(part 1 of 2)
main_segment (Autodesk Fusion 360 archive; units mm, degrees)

design "main_segment" references "mounting plate"
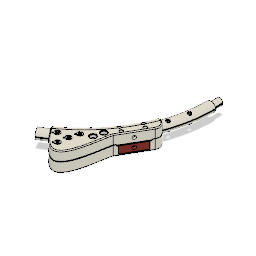
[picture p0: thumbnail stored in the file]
sketch "profile25mm" plane through (0, 0, 0) normal (0, 0, 1) x axis (1, 0, 0)
  line L1 (307.6864, 0) -> (0, 0)
  line L2 (284.5852, 6.2462) -> (284.5852, -6.2452)
  line L3 (286.5852, -8.1498) -> (286.5852, 8.1498)
  line L4 (286.6852, -8.0748) -> (286.6852, 8.0748)
  line L5 (288.5852, -6.4868) -> (288.5852, 6.4868)
  line L6 (281.1852, 6.0452) -> (281.1852, 6.2452)
  line L7 (280.7852, 5.8452) -> (280.9852, 5.8452)
  line L8 (280.3368, 6.812) -> (280.7852, 7.3155)
  line L9 (281.1852, -6.0452) -> (281.1852, -6.2452)
  line L10 (280.7852, -5.8452) -> (280.9852, -5.8452)
  line L11 (280.3368, -6.812) -> (280.7852, -7.3155)
  line L12 (284.1852, 5.6456) -> (284.1852, 6.2456)
  line L13 (282.5852, 5.4456) -> (283.9852, 5.4456)
  line L14 (282.3852, 6.2456) -> (282.3852, 5.6456)
  line L15 (284.1852, -5.6452) -> (284.1852, -6.2452)
  line L16 (282.5852, -5.4452) -> (283.9852, -5.4452)
  line L17 (282.3852, -6.2452) -> (282.3852, -5.6452)
  line L18 (282.3852, 6.2456) -> (281.1852, 6.2452)
  line L19 (284.5852, 6.2462) -> (284.1852, 6.2456)
  line L20 (282.3852, -6.2452) -> (281.1852, -6.2452)
  line L21 (284.5852, -6.2452) -> (284.1852, -6.2452)
  arc A1 centre (289, 0) radius 8.5 clockwise from (286.5852, 8.1498) to (286.5852, -8.1498)
  arc A2 centre (289, 0) radius 11 clockwise from (280.7852, 7.3155) to (280.7852, -7.3155)
  arc A3 centre (289, 0) radius 8.4 clockwise from (286.6852, 8.0748) to (286.6852, -8.0748)
  arc A4 centre (289, 0) radius 6.5 clockwise from (288.5852, 6.4868) to (288.5852, -6.4868)
  arc A5 centre (280.7705, 6.4258) radius 0.5808 clockwise from (280.7852, 5.8452) to (280.3368, 6.812)
  arc A6 centre (280.7705, -6.4258) radius 0.5808 clockwise from (280.3368, -6.812) to (280.7852, -5.8452)
  arc A7 centre (282.5852, 5.6456) radius 0.2 clockwise from (282.5852, 5.4456) to (282.3852, 5.6456)
  arc A8 centre (283.9852, 5.6456) radius 0.2 clockwise from (284.1852, 5.6456) to (283.9852, 5.4456)
  arc A9 centre (282.5852, -5.6452) radius 0.2 clockwise from (282.3852, -5.6452) to (282.5852, -5.4452)
  arc A10 centre (283.9852, -5.6452) radius 0.2 clockwise from (283.9852, -5.4452) to (284.1852, -5.6452)
  arc A11 centre (280.9852, -6.0452) radius 0.2 clockwise from (280.9852, -5.8452) to (281.1852, -6.0452)
  arc A12 centre (280.9852, 6.0452) radius 0.2 clockwise from (281.1852, 6.0452) to (280.9852, 5.8452)
  point P1 (0, 0)
  point P3 (0, 0)
  point P2 (289, 0)
  point P17 (280.7852, 7.3155)
  point P26 (280.7852, -7.3155)
  point P19 (280.7852, 5.8452)
  point P23 (280.7852, -5.8452)
  point P20 (280.3368, 6.812)
  point P25 (280.3368, -6.812)
  point P29 (282.3852, 5.4456)
  point P33 (282.3852, -5.4452)
  point P32 (284.1852, -5.4452)
  point P7 (289, 0)
  point P27 (282.3852, 6.2456)
  point P28 (284.1852, 6.2456)
  point P30 (282.3852, -6.2452)
  coincident P1 P3
  horizontal L1
  coincident P2 L1
  concentric A1 A2
  perpendicular L1 L3
  horizontal L20
  vertical L6
  horizontal L7
  tangent A2 L8
  tangent L8 A5
  vertical L9
  horizontal L10
  symmetric L1 P17 P26
  symmetric L1 P19 P23
  symmetric L1 P20 P25
  symmetric L1 A5 A6
  vertical L12
  horizontal L13
  vertical L14
  vertical L15
  horizontal L16
  vertical L17
  coincident P29 L13
  coincident P29 L14
  tangent L13 A7
  tangent L14 A7
  tangent L12 A8
  tangent L13 A8
  equal A7 A8
  coincident P33 L16
  coincident P33 L17
  tangent L16 A9
  tangent L17 A9
  equal A7 A9
  coincident P32 L15
  coincident P32 L16
  tangent L15 A10
  tangent L16 A10
  equal A7 A10
  tangent L9 A11
  tangent L10 A11
  equal A7 A11
  tangent L6 A12
  tangent L7 A12
  equal A7 A12
  collinear L20 L21
  dimension "d1" diameter A2 = 22
  dimension "d5" diameter A1 = 17
  dimension "d10" distance L2 L3 = 2
  dimension "d11" = -0.1
  dimension "d12" = -2
  dimension "d13" distance P1 P7 = 289
  dimension "d58" distance P27 P28 = 1.8
  dimension "d59" distance P27 P29 = 0.8
  dimension "d60" distance L2 L12 = 0.4
  dimension "d61" distance P32 P33 = 1.8
  dimension "d62" distance P30 P33 = 0.8
  dimension "d63" distance L2 L15 = 0.4
  dimension "d64" radius A7 = 0.2
revolve "Revolve1" sketch "profile25mm" AlongAngle 60 bodies "profile"
revolve "Revolve2" sketch "profile25mm" AlongAngle 4
revolve "Revolve3" sketch "profile25mm" AlongAngle -4
chamfer "Chamfer1" distance 1
chamfer "Chamfer2" distance 1.9
work_plane "WorkPlane1"
sketch "middle plane" plane through (272.3575, 0.0002, 35.882) normal (0, -1, 0) x axis (1, 0, 0)
  line L1 (-131.9649, 207.2851) -> (-122.3575, 223.9256)
  line L2 (14.6269, -55.9499) -> (23.3204, -56.5578)
  line L3 (13.6973, -54.8824) -> (14.6269, -55.9499)
  line L4 (25.0425, -35.882) -> (27.6425, -35.882)
  line L5 (8.4277, -35.882) -> (14.3277, -35.882)
  line L6 (24.3861, -55.6299) -> (23.3204, -56.5578)
  line L7 (-115.0265, 216.6233) -> (-113.7806, 218.7813)
  line L8 (17.5, -45.882) -> (24.8743, -45.882)
  line L9 (-132.1891, 206.8968) -> (-131.9649, 207.2851)
  line L10 (-132.2627, 206.7695) -> (-132.1891, 206.8968)
  line L11 (7.8322, -35.882) -> (7.9792, -35.882)
  line L12 (7.9792, -35.882) -> (8.4277, -35.882)
  arc A1 centre (-272.3575, -35.882) radius 286.6852 clockwise from (14.3277, -35.882) to (13.6973, -54.8824)
  arc A2 centre (-272.3575, -35.882) radius 297.4 clockwise from (25.0425, -35.882) to (24.3861, -55.6299)
  arc A3 centre (-272.3575, -35.882) radius 300 clockwise from (-122.3575, 223.9256) to (27.6425, -35.882)
  arc A4 centre (-272.3575, -35.882) radius 280.1897 clockwise from (-132.2627, 206.7695) to (7.8322, -35.882)
  point P14 (-113.7806, 218.7813)
  point P16 (24.8743, -45.882)
  coincident A3 P14
  parallel L1 L7
  coincident A2 P16
  parallel L4 L8
  dimension "d25" distance L1 L7 = 10
  dimension "d33" distance L4 L8 = 10
work_plane "WorkPlane2"
sketch "hole1" plane through (158.5769, 0.0002, 254.6632) normal (0.5286, 0, 0.8489) x axis (0, 1, 0)
  circle C1 centre (0, 0) radius 2.05
  circle C2 centre (0, 0) radius 1.05
  point P1 (0, 0)
  point P2 (0, 0)
  coincident P1 P2
  concentric C1 C2
  dimension "d26" diameter C1 = 4.1
  dimension "d27" diameter C2 = 2.1
extrude "Extrude2" cut sketch "hole1" along a picked direction blind -1
extrude "Extrude3" cut sketch "hole1" profile of C2 along a picked direction blind -3
work_plane "WorkPlane3"
sketch "hole2" plane through (297.2318, 0.0002, -10) normal (0.9994, 0, -0.0336) x axis (0, 1, 0)
  line L1 (0, 2.3094) -> (2, 1.1547)
  line L2 (-2, 1.1547) -> (0, 2.3094)
  line L3 (-2, -1.1547) -> (-2, 1.1547)
  line L4 (0, -2.3094) -> (-2, -1.1547)
  line L5 (2, -1.1547) -> (0, -2.3094)
  line L6 (2, 1.1547) -> (2, -1.1547)
  circle C1 centre (0, 0) radius 1.05
  circle C2 centre (0, 0) radius 4
  point P1 (0, 0)
  point P2 (0, 0)
  point P3 (0, 0)
  point P10 (0, 0)
  coincident P1 P2
  coincident P1 P3
  coincident P3 P10
  dimension "d34" diameter C1 = 2.1
  dimension "d37" diameter C2 = 8
extrude "Extrude4" cut sketch "hole2" profile of C1 against normal blind 3
extrude "Extrude5" add sketch "hole2" profile of C2 L1 L2 L3 L4 L5 L6 blind -1.6 from offset -2
chamfer "Chamfer3" distance 0.5
sketch "box" plane through (212.6389, 0.0002, 122.9692) normal (0, -1, 0) x axis (1, 0, 0)
  line L1 (47.1687, 27.0308) -> (30.0125, 17.1257)
  line L2 (59.9833, 34.4293) -> (47.1687, 27.0308)
  line L3 (74.9833, 8.4485) -> (44.9833, 60.4101)
  line L4 (43.6176, -9.6604) -> (74.9833, 8.4485)
  line L5 (13.6176, 42.3011) -> (44.9833, 60.4101)
  line L6 (69.7872, 5.4485) -> (39.7871, 57.4101)
  line L7 (59.3948, -0.5515) -> (29.3948, 51.4101)
  line L8 (84.9833, -8.872) -> (59.9833, 34.4293)
  line L9 (51.1177, -28.4243) -> (84.9833, -8.872)
  line L10 (42.4833, 64.7402) -> (59.9833, 34.4293)
  curve K1 (-40.9263, 123.0284) -> (42.4833, 64.7402)
  curve K2 (-56.6539, 100.4929) -> (-25.1987, 145.5638)
  line L11 (-52.3554, 106.847) -> (-40.9263, 123.0284)
  line L12 (-48.9096, 104.4132) -> (-55.8012, 109.2808)
  curve K3 (41.3534, 66.6972) -> (43.6132, 62.7832)
  arc A1 centre (-212.6389, -122.9692) radius 280.1897 clockwise from (-72.544, 119.6822) to (67.5508, -122.9692)
  arc A2 centre (-212.6389, -122.9692) radius 300 clockwise from (-62.6389, 136.8384) to (87.3611, -122.9692)
  arc A3 centre (-212.6389, -122.9692) radius 300 clockwise from (-62.6389, 136.8384) to (87.3611, -122.9692)
  arc A4 centre (-212.6389, -122.9692) radius 296 clockwise from (-64.6389, 133.3743) to (83.3611, -122.9692)
  arc A5 centre (-212.6389, -122.9692) radius 280.1897 clockwise from (-52.3554, 106.847) to (51.1177, -28.4243)
  circle C1 centre (-25.4657, 106.3389) radius 8.75
  circle C2 centre (-9.5921, 92.4095) radius 8.75
  circle C3 centre (4.9476, 77.71) radius 8.75
  circle C4 centre (18.225, 62.2816) radius 8.75
  circle C5 centre (64.7872, 14.1088) radius 2.05
  circle C6 centre (44.7871, 48.7498) radius 2.05
  circle C7 centre (34.3948, 42.7498) radius 2.05
  circle C8 centre (54.3948, 8.1088) radius 2.05
  point P8 (30.0125, 17.1257)
  point P9 (47.1687, 27.0308)
  point P13 (59.9833, 34.4293)
  point P16 (43.6176, -9.6604)
  point P17 (13.6176, 42.3011)
  point P18 (39.7871, 57.4101)
  point P19 (69.7872, 5.4485)
  point P20 (29.3948, 51.4101)
  point P21 (59.3948, -0.5515)
  point P23 (51.1177, -28.4243)
  point P28 (-40.9263, 123.0284)
  point P31 (-52.3554, 106.847)
  point P2 (67.5508, -122.9692)
  point P35 (-25.4657, 106.3389)
  point P36 (-9.5921, 92.4095)
  point P37 (4.9476, 77.71)
  point P38 (18.225, 62.2816)
  point P39 (64.7872, 14.1088)
  point P40 (44.7871, 48.7498)
  point P41 (34.3948, 42.7498)
  point P42 (54.3948, 8.1088)
  point P24 (42.4833, 64.7402)
  point P14 (44.9833, 60.4101)
  point P15 (74.9833, 8.4485)
  point P22 (84.9833, -8.872)
  midpoint A1 P8
  midpoint A2 P9
  midpoint P13 L3
  perpendicular L2 L3
  coincident A1 P16
  perpendicular L3 L4
  coincident A1 P17
  perpendicular L3 L5
  coincident L5 P18
  coincident L4 P19
  perpendicular L4 L6
  coincident L5 P20
  coincident L4 P21
  perpendicular L4 L7
  perpendicular L4 L8
  coincident A1 P23
  perpendicular L8 L9
  perpendicular L2 L10
  coincident A3 P28
  midpoint P28 K2
  coincident A1 P31
  midpoint P31 L12
  perpendicular L11 L12
  concentric A1 A5
  coincident P2 A5
  coincident A4 P35
  coincident A4 P36
  coincident A4 P37
  coincident A4 P38
  coincident L6 P39
  coincident L6 P40
  coincident L7 P41
  coincident L7 P42
  midpoint P24 K3
  dimension "d66" distance P9 P13 = 14.797 (= "17.297 mm - 2.5 mm")
  dimension "d67" distance P14 P15 = 60
  dimension "d68" distance L3 L6 = 6
  dimension "d69" distance L3 L7 = 18
  dimension "d70" distance P13 P22 = 50
  dimension "d71" distance P13 P24 = 35
  dimension "d72" = -4
  dimension "d73" diameter C1 = 17.5
  dimension "d74" diameter C2 = 17.5
  dimension "d75" diameter C3 = 17.5
  dimension "d76" diameter C4 = 17.5
  dimension "d77" distance L5 P35 = 75
  dimension "d78" distance L5 P36 = 55
  dimension "d79" distance L5 P37 = 35
  dimension "d80" distance L5 P38 = 15
  dimension "d81" diameter C5 = 4.1
  dimension "d82" diameter C6 = 4.1
  dimension "d83" diameter C7 = 4.1
  dimension "d84" diameter C8 = 4.1
  dimension "d85" distance L4 P42 = 10
  dimension "d86" distance L4 P39 = 10
  dimension "d87" distance L5 P40 = 10
  dimension "d88" distance L5 P41 = 10
extrude "Extrude7" new body sketch "box" profile of L8 L9 L10 K1 L11 A5 C1 C2 C3 C4 C5 C6 C7 C8 distance 22
fillet "Fillet1" radius 20
fillet "Fillet2" radius 15
combine "Combine1"
delete_face "DeleteFace1"
chamfer "Chamfer1" distance 2
revolve "Revolve1" sketch "profile25mm" AlongAngle 55
split "Split1"
extrude "Extrude1" cut sketch "box" profile of C7 C8 along normal blind 41
component_insert "Component Insert"
position "Position1"
combine "Combine2"
sketch "pocket" plane through (0, 0.0002, 0) normal (0, 1, 0) x axis (-1, 0, 0)
  curve K1 (-171.7126, 245.9976) -> (-255.1222, 187.7094)
  curve K2 (-174.1727, 244.2806) -> (-252.5241, 186.2094)
  line L1 (-240.9703, 179.5388) -> (-252.5241, 186.2094)
  line L2 (-174.1727, 244.2806) -> (-182.7946, 238.5269)
  line L3 (-284.2856, 37.2412) -> (-294.6402, 38.6044)
  line L4 (-180.9692, 236.1462) -> (-174.3946, 227.5779)
  line L5 (-257.6222, 183.3793) -> (-241.3298, 173.9728)
  line L6 (-287.6222, 131.4177) -> (-257.6222, 183.3793)
  line L7 (-271.3298, 122.0113) -> (-287.6222, 131.4177)
  line L8 (-294.7423, 38.6178) -> (-294.9932, 38.6508)
  line L9 (-278.6777, 103.1596) -> (-278.7681, 103.2118)
  line L10 (-237.4716, 168.2812) -> (-259.1222, 180.7812)
  line L11 (-264.4716, 121.5158) -> (-286.1222, 134.0158)
  line L12 (-264.4716, 121.5158) -> (-237.4716, 168.2812)
  line L13 (-265.9716, 118.9177) -> (-264.4716, 121.5158)
  line L14 (-269.4357, 120.9177) -> (-265.9716, 118.9177)
  line L15 (-267.9357, 123.5158) -> (-269.4357, 120.9177)
  line L16 (-235.9716, 170.8793) -> (-237.4716, 168.2812)
  line L17 (-239.4357, 172.8793) -> (-235.9716, 170.8793)
  line L18 (-240.9357, 170.2812) -> (-239.4357, 172.8793)
  arc A1 centre (0.1681, -0.0971) radius 297.6938 clockwise from (-241.3298, 173.9728) to (-180.9692, 236.1462)
  arc A2 centre (0.1681, -0.0971) radius 300.6938 clockwise from (-240.9703, 179.5388) to (-182.7946, 238.5269)
  arc A3 centre (0, 0) radius 297.1585 clockwise from (-294.6402, 38.6044) to (-278.6777, 103.1596)
  arc A4 centre (0.1681, -0.0971) radius 286.8938 clockwise from (-284.2856, 37.2412) to (-174.3946, 227.5779)
  arc A5 centre (0.1681, -0.0971) radius 297.6938 clockwise from (-241.3298, 173.9728) to (-180.9692, 236.1462)
  arc A6 centre (0.1681, -0.0971) radius 297.6938 clockwise from (-294.9932, 38.6508) to (-271.3298, 122.0113)
  arc A7 centre (0, 0) radius 297.2614 clockwise from (-294.7423, 38.6178) to (-278.7681, 103.2118)
  circle C1 centre (-214.7385, 198.0211) radius 2
  circle C2 centre (-278.8606, 86.9584) radius 2
  circle C3 centre (-185.5135, 225.6417) radius 2
  circle C4 centre (-288.1682, 47.8386) radius 2
  circle C5 centre (-247.0337, 165.719) radius 2.05
  circle C6 centre (-267.0337, 131.078) radius 2.05
  circle C7 centre (-257.426, 171.719) radius 2.05
  circle C8 centre (-277.426, 137.078) radius 2.05
  point P34 (-259.1222, 180.7812)
  point P36 (-286.1222, 134.0158)
  point P40 (-267.9357, 123.5158)
  point P43 (-240.9357, 170.2812)
  point P35 (-237.4716, 168.2812)
  point P37 (-264.4716, 121.5158)
  point P38 (-265.9716, 118.9177)
  point P39 (-269.4357, 120.9177)
  point P41 (-235.9716, 170.8793)
  point P42 (-239.4357, 172.8793)
  concentric A1 A2
  coincident L6 P34
  perpendicular L6 L10
  coincident L6 P36
  perpendicular L6 L11
  perpendicular L11 L13
  perpendicular L13 L14
  coincident L11 P40
  perpendicular L11 L15
  perpendicular L10 L16
  perpendicular L16 L17
  coincident L10 P43
  perpendicular L10 L18
  dimension "d101" = 3
  dimension "d107" distance P34 P35 = 25
  dimension "d108" distance P36 P37 = 25
  dimension "d109" distance L7 L11 = 3
  dimension "d110" distance L5 L10 = 3
  dimension "d111" distance P37 P38 = 3
  dimension "d112" distance P38 P39 = 4
  dimension "d113" distance P35 P41 = 3
  dimension "d114" distance P41 P42 = 4
extrude "Extrude3" cut sketch "pocket" profile of K2 A2 L1 L2 against normal blind 15
extrude "Extrude4" cut of existing geometry distance 30
sketch "mounting block" plane through (0, -1.9998, 0) normal (0, 1, 0) x axis (-1, 0, 0)
  line L1 (-284.2856, 37.2412) -> (-294.6402, 38.6044)
  line L2 (-180.9692, 236.1462) -> (-174.3946, 227.5779)
  line L3 (-257.6222, 183.3793) -> (-241.3298, 173.9728)
  line L4 (-287.6222, 131.4177) -> (-257.6222, 183.3793)
  line L5 (-271.3298, 122.0113) -> (-287.6222, 131.4177)
  line L6 (-294.7423, 38.6178) -> (-294.9932, 38.6508)
  line L7 (-278.6777, 103.1596) -> (-278.7681, 103.2118)
  line L8 (-270.0308, 121.2613) -> (-271.3298, 122.0113)
  line L9 (-270.8478, 118.8463) -> (-269.8478, 120.5783)
  line L10 (-269.4327, 116.2972) -> (-270.2987, 116.7972)
  line L11 (-240.0308, 173.2228) -> (-241.3298, 173.9728)
  line L12 (-238.3478, 175.1379) -> (-239.3478, 173.4059)
  line L13 (-235.4327, 175.1869) -> (-236.2987, 175.6869)
  line L14 (-267.3837, 116.8463) -> (-234.8837, 173.1379)
  line L15 (-274.1988, 123.6677) -> (-271.3298, 122.0113)
  line L16 (-285.6222, 134.8818) -> (-284.3189, 130.0179)
  line L17 (-259.6222, 179.9152) -> (-285.6222, 134.8818)
  line L18 (-254.7582, 181.2185) -> (-259.6222, 179.9152)
  line L19 (-250.261, 179.1293) -> (-253.62, 181.0686)
  line L20 (-246.7478, 174.2142) -> (-246.2478, 175.0802)
  line L21 (-249.6629, 174.1652) -> (-248.7969, 173.6652)
  line L22 (-248.9619, 178.3793) -> (-250.2119, 176.2142)
  line L23 (-245.8228, 174.9152) -> (-250.9619, 174.9152)
  line L24 (-274.2478, 126.5828) -> (-274.7478, 125.7168)
  line L25 (-275.6629, 129.1318) -> (-274.7969, 128.6318)
  line L26 (-250.9619, 174.9152) -> (-249.7119, 177.0802)
  line L27 (-278.2119, 127.7168) -> (-277.7119, 128.5828)
  line L28 (-283.62, 129.1071) -> (-280.261, 127.1677)
  line L29 (-241.3298, 173.9728) -> (-244.1988, 175.6293)
  line L30 (-250.344, 176.1855) -> (-250.2988, 176.2638)
  line L31 (-249.7983, 177.1307) -> (-250.2985, 176.2642)
  line L32 (-250.311, 179.0427) -> (-253.67, 180.982)
  line L33 (-254.7324, 181.1219) -> (-259.5563, 179.8293)
  line L34 (-259.5563, 179.8293) -> (-285.5149, 134.8677)
  line L35 (-285.5149, 134.8677) -> (-284.2223, 130.0438)
  line L36 (-283.57, 129.1937) -> (-280.211, 127.2543)
  line L37 (-278.2985, 127.7668) -> (-277.7985, 128.6328)
  line L38 (-275.6129, 129.2184) -> (-274.7469, 128.7184)
  line L39 (-274.1612, 126.5328) -> (-274.6612, 125.6668)
  line L40 (-274.1488, 123.7543) -> (-271.2798, 122.0979)
  line L41 (-269.9808, 121.3479) -> (-271.2798, 122.0979)
  line L42 (-270.7612, 118.7963) -> (-269.7612, 120.5283)
  line L43 (-269.3827, 116.3838) -> (-270.2487, 116.8838)
  line L44 (-267.4703, 116.8963) -> (-234.9703, 173.1879)
  line L45 (-235.4827, 175.1003) -> (-236.3487, 175.6003)
  line L46 (-238.2612, 175.0879) -> (-239.2612, 173.3559)
  line L47 (-240.0808, 173.1362) -> (-241.3798, 173.8862)
  line L48 (-241.3798, 173.8862) -> (-244.2488, 175.5427)
  line L49 (-246.6612, 174.1642) -> (-246.1612, 175.0302)
  line L50 (-249.7129, 174.0786) -> (-248.8469, 173.5786)
  line L51 (-249.7129, 174.0786) -> (-249.8745, 174.1858)
  arc A1 centre (0, 0) radius 297.1585 clockwise from (-294.6402, 38.6044) to (-278.6777, 103.1596)
  arc A2 centre (0.1681, -0.0971) radius 286.8938 clockwise from (-284.2856, 37.2412) to (-174.3946, 227.5779)
  arc A3 centre (0.1681, -0.0971) radius 297.6938 clockwise from (-241.3298, 173.9728) to (-180.9692, 236.1462)
  arc A4 centre (0.1681, -0.0971) radius 297.6938 clockwise from (-294.9932, 38.6508) to (-271.3298, 122.0113)
  arc A5 centre (0, 0) radius 297.2614 clockwise from (-294.7423, 38.6178) to (-278.7681, 103.2118)
  circle C1 centre (-214.7385, 198.0211) radius 2
  circle C2 centre (-278.8606, 86.9584) radius 2
  circle C3 centre (-185.5135, 225.6417) radius 2
  circle C4 centre (-288.1682, 47.8386) radius 2
  circle C5 centre (-247.0337, 165.719) radius 2.05
  circle C6 centre (-267.0337, 131.078) radius 2.05
  circle C7 centre (-257.426, 171.719) radius 2.05
  circle C8 centre (-277.426, 137.078) radius 2.05
  arc A6 centre (-268.6827, 117.5963) radius 1.5 clockwise from (-267.3837, 116.8463) to (-269.4327, 116.2972)
  arc A7 centre (-269.5487, 118.0963) radius 1.5 clockwise from (-270.2987, 116.7972) to (-270.8478, 118.8463)
  arc A8 centre (-236.1827, 173.8879) radius 1.5 clockwise from (-235.4327, 175.1869) to (-234.8837, 173.1379)
  arc A9 centre (-237.0487, 174.3879) radius 1.5 clockwise from (-238.3478, 175.1379) to (-236.2987, 175.6869)
  arc A10 centre (-254.37, 179.7696) radius 1.5 clockwise from (-254.7582, 181.2185) to (-253.62, 181.0686)
  arc A11 centre (-282.87, 130.4061) radius 1.5 clockwise from (-283.62, 129.1071) to (-284.3189, 130.0179)
  arc A12 centre (-248.0469, 174.9642) radius 1.5 clockwise from (-246.7478, 174.2142) to (-248.7969, 173.6652)
  arc A13 centre (-248.9129, 175.4642) radius 1.5 clockwise from (-249.6629, 174.1652) to (-250.2119, 176.2142)
  arc A14 centre (-275.5469, 127.3328) radius 1.5 clockwise from (-274.7969, 128.6318) to (-274.2478, 126.5828)
  arc A15 centre (-276.4129, 127.8328) radius 1.5 clockwise from (-277.7119, 128.5828) to (-275.6629, 129.1318)
  arc A16 centre (-273.4488, 124.9668) radius 1.5 clockwise from (-274.1988, 123.6677) to (-274.7478, 125.7168)
  arc A17 centre (-251.011, 177.8302) radius 1.5 clockwise from (-250.261, 179.1293) to (-249.7119, 177.0802)
  arc A18 centre (-279.511, 128.4668) radius 1.5 clockwise from (-278.2119, 127.7168) to (-280.261, 127.1677)
  arc A19 centre (-244.9488, 174.3302) radius 1.5 clockwise from (-246.2478, 175.0802) to (-244.1988, 175.6293)
  arc A20 centre (-270.2808, 120.8283) radius 0.5 clockwise from (-270.0308, 121.2613) to (-269.8478, 120.5783)
  arc A21 centre (-239.7808, 173.6559) radius 0.5 clockwise from (-239.3478, 173.4059) to (-240.0308, 173.2228)
  arc A22 centre (-248.9129, 175.4642) radius 1.6 clockwise from (-250.2988, 176.2638) to (-250.2985, 176.2642)
  arc A23 centre (-251.011, 177.8302) radius 1.4 clockwise from (-250.311, 179.0427) to (-249.7983, 177.1307)
  arc A24 centre (-254.37, 179.7696) radius 1.4 clockwise from (-254.7324, 181.1219) to (-253.67, 180.982)
  arc A25 centre (-282.87, 130.4061) radius 1.4 clockwise from (-283.57, 129.1937) to (-284.2223, 130.0438)
  arc A26 centre (-279.511, 128.4668) radius 1.4 clockwise from (-278.2985, 127.7668) to (-280.211, 127.2543)
  arc A27 centre (-276.4129, 127.8328) radius 1.6 clockwise from (-277.7985, 128.6328) to (-275.6129, 129.2184)
  arc A28 centre (-275.5469, 127.3328) radius 1.6 clockwise from (-274.7469, 128.7184) to (-274.1612, 126.5328)
  arc A29 centre (-273.4488, 124.9668) radius 1.4 clockwise from (-274.1488, 123.7543) to (-274.6612, 125.6668)
  arc A30 centre (-270.2808, 120.8283) radius 0.6 clockwise from (-269.9808, 121.3479) to (-269.7612, 120.5283)
  arc A31 centre (-269.5487, 118.0963) radius 1.4 clockwise from (-270.2487, 116.8838) to (-270.7612, 118.7963)
  arc A32 centre (-268.6827, 117.5963) radius 1.4 clockwise from (-267.4703, 116.8963) to (-269.3827, 116.3838)
  arc A33 centre (-236.1827, 173.8879) radius 1.4 clockwise from (-235.4827, 175.1003) to (-234.9703, 173.1879)
  arc A34 centre (-237.0487, 174.3879) radius 1.4 clockwise from (-238.2612, 175.0879) to (-236.3487, 175.6003)
  arc A35 centre (-239.7808, 173.6559) radius 0.6 clockwise from (-239.2612, 173.3559) to (-240.0808, 173.1362)
  arc A36 centre (-244.9488, 174.3302) radius 1.4 clockwise from (-246.1612, 175.0302) to (-244.2488, 175.5427)
  arc A37 centre (-248.0469, 174.9642) radius 1.6 clockwise from (-246.6612, 174.1642) to (-248.8469, 173.5786)
  arc A38 centre (-249.0449, 175.4355) radius 1.5 clockwise from (-249.8745, 174.1858) to (-250.344, 176.1855)
  point P12 (-271.3298, 122.0113)
  point P24 (-271.3298, 122.0113)
  point P9 (-241.3298, 173.9728)
  point P28 (-241.3298, 173.9728)
  point P32 (-271.3298, 122.0113)
  point P33 (-284.1581, 129.4177)
  point P34 (-285.6222, 134.8818)
  point P35 (-259.6222, 179.9152)
  point P36 (-254.1581, 181.3793)
  point P27 (-268.1337, 115.5472)
  point P26 (-271.5978, 117.5472)
  point P31 (-234.1337, 174.4369)
  point P30 (-237.5978, 176.4369)
  point P55 (-245.4978, 176.3793)
  point P60 (-275.4978, 124.4177)
  point P63 (-278.9619, 126.4177)
  point P56 (-247.4978, 172.9152)
  point P57 (-250.9619, 174.9152)
  point P61 (-273.4978, 127.8818)
  point P62 (-276.9619, 129.8818)
  point P52 (-283.62, 129.1071)
  point P74 (-277.7119, 128.5828)
  point P85 (-241.3298, 173.9728)
  point P25 (-269.5978, 121.0113)
  point P29 (-239.5978, 172.9728)
  point P10 (-257.6222, 183.3793)
  point P58 (-248.9619, 178.3793)
  coincident P12 P24
  parallel L5 L8
  perpendicular L8 L9
  perpendicular L9 L10
  coincident P9 P28
  parallel L3 L11
  perpendicular L11 L12
  perpendicular L12 L13
  coincident P12 P32
  coincident L5 P33
  parallel L5 L15
  coincident L4 P34
  coincident L4 P35
  perpendicular L5 L17
  coincident L3 P36
  coincident P27 L10
  coincident P27 L14
  tangent L10 A6
  tangent L14 A6
  coincident P26 L9
  coincident P26 L10
  tangent L9 A7
  tangent L10 A7
  equal A6 A7
  coincident P31 L13
  coincident P31 L14
  tangent L13 A8
  tangent L14 A8
  equal A6 A8
  coincident P30 L12
  coincident P30 L13
  tangent L12 A9
  tangent L13 A9
  equal A6 A9
  coincident P36 L18
  coincident P36 L19
  tangent L18 A10
  tangent L19 A10
  equal A6 A10
  coincident P33 L16
  tangent L15 A11
  tangent L16 A11
  equal A6 A11
  coincident L3 P55
  perpendicular L19 L20
  perpendicular L20 L21
  horizontal L23
  coincident L5 P60
  perpendicular L5 L24
  perpendicular L24 L25
  coincident L15 P63
  coincident P56 L21
  coincident P56 L20
  tangent L21 A12
  tangent L20 A12
  coincident P57 L21
  coincident P57 L22
  tangent L21 A13
  tangent L22 A13
  equal A12 A13
  coincident P61 L24
  tangent L24 A14
  tangent L25 A14
  equal A12 A14
  coincident P62 L25
  coincident P62 L26
  tangent L25 A15
  tangent A15 L26
  equal A12 A15
  coincident P60 L24
  coincident L15 P52
  tangent L24 A16
  tangent L15 A16
  equal A12 A16
  coincident P74 L26
  tangent A17 L26
  tangent L19 A17
  equal A12 A17
  collinear L26 L27
  coincident P63 L27
  coincident P63 L28
  tangent L27 A18
  tangent L28 A18
  coincident P9 P85
  perpendicular L20 L29
  coincident P55 L20
  coincident P55 L29
  tangent L20 A19
  tangent L29 A19
  coincident P25 L8
  coincident P25 L9
  tangent L8 A20
  tangent L9 A20
  coincident P29 L11
  coincident P29 L12
  tangent L11 A21
  tangent L12 A21
  equal A20 A21
  parallel L26 L30
  concentric A13 A22
  parallel L22 L31
  concentric A17 A23
  parallel L19 L32
  concentric A10 A24
  parallel L18 L33
  parallel L17 L34
  parallel L16 L35
  concentric A11 A25
  parallel L28 L36
  concentric A18 A26
  parallel L27 L37
  concentric A15 A27
  parallel L25 L38
  concentric A14 A28
  parallel L24 L39
  concentric A16 A29
  parallel L15 L40
  parallel L8 L41
  concentric A20 A30
  parallel L9 L42
  concentric A7 A31
  parallel L10 L43
  concentric A6 A32
  parallel L14 L44
  concentric A8 A33
  parallel L13 L45
  concentric A9 A34
  parallel L12 L46
  concentric A21 A35
  parallel L11 L47
  parallel L29 L48
  concentric A19 A36
  parallel L20 L49
  concentric A12 A37
  parallel L21 L50
  tangent A36 L49
  tangent A34 L46
  tangent A24 L33
  tangent A26 L37
  tangent A23 L32
  tangent A22 L31
  tangent A31 L43
  tangent L32 A24
  tangent L35 A25
  tangent L37 A27
  tangent A25 L36
  tangent L45 A34
  tangent L36 A26
  tangent A27 L38
  tangent L38 A28
  tangent A28 L39
  tangent L39 A29
  tangent A29 L40
  tangent L41 A30
  tangent A30 L42
  tangent L42 A31
  tangent L43 A32
  tangent A32 L44
  tangent L44 A33
  tangent A33 L45
  tangent L46 A35
  tangent A35 L47
  tangent L48 A36
  tangent L49 A37
  tangent A37 L50
  tangent L30 A38
  tangent L51 A38
  dimension "d115" distance P25 P26 = 4
  dimension "d116" distance P26 P27 = 4
  dimension "d117" distance P28 P29 = 2
  dimension "d118" distance P29 P30 = 4
  dimension "d119" distance P30 P31 = 4
  dimension "d120" distance P10 P35 = 4
  dimension "d121" distance L4 P36 = 4
  dimension "d122" distance L4 P33 = 4
  dimension "d123" distance L5 P34 = 4
  dimension "d124" radius A6 = 1.5
  dimension "d125" distance P55 P56 = 4
  dimension "d126" distance P56 P57 = 4
  dimension "d127" angle L22 L23 = 60
  dimension "d128" distance P57 P58 = 4
  dimension "d129" distance P60 P61 = 4
  dimension "d130" distance P61 P62 = 4
  dimension "d131" distance P62 P63 = 4
  dimension "d132" distance L4 L26 = 10
  dimension "d133" distance L17 L22 = 10
  dimension "d134" radius A12 = 1.5
  dimension "d135" radius A18 = 1.5
  dimension "d136" radius A19 = 1.5
  dimension "d137" distance P24 P25 = 2
  dimension "d138" radius A20 = 0.5
  dimension "d142" radius A38 = 1.5
extrude "Extrude5" cut sketch "mounting block" profile of L3 L4 L5 C5 C6 C7 C8 L8 L9 L10 L11 L12 L13 L14 L15 L16 L17 L18 L19 A6 A7 A8 A9 A10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 against normal blind 16
extrude "Extrude8" new body sketch "mounting block" profile of C5 C6 C7 C8 L42 L30 L34 A30 A22 A24 A36 L31 L33 A23 L36 L35 L32 A25 A31 A26 L37 A27 L38 A35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 along normal blind 16 bodies "mounting block"
extrude "Extrude9" add of existing geometry blind 0.1
hole "Hole1" HoleDepth 6 HoleDiameter 5 TipAngle 180 RefDim1 7.5 RefDim2 25.9585 (= "( 51.917 / 2 ) * 1 mm")
move "Move1"
extrude "Extrude6" cut sketch "pocket" profile of K2 A2 L1 L2 along normal blind 15
hole "Hole1" HoleDepth 30 HoleDiameter 4.1 TipAngle 180
hole "Hole2" HoleDepth 30 HoleDiameter 4.1 TipAngle 180
sketch "potentiometers" plane through (0, 15.0002, 0) normal (0, -1, 0) x axis (1, 0, 0)
  line L1 (187.4095, 246.5491) -> (191.4109, 250.6785)
  line L2 (201.1296, 251.0084) -> (191.4345, 260.4028)
  line L3 (196.1474, 246.0889) -> (186.6743, 255.2682)
  line L4 (188.1448, 237.8301) -> (178.6716, 247.0094)
  line L5 (183.4959, 252.5694) -> (182.345, 253.6845)
  line L6 (181.269, 250.2713) -> (183.4959, 252.5694)
  line L7 (180.1182, 251.3864) -> (181.269, 250.2713)
  line L8 (181.1257, 252.6381) -> (187.4095, 246.5491)
  line L9 (190.0204, 260.3806) -> (184.6705, 254.8594)
  line L10 (201.1519, 249.5944) -> (195.8019, 244.0732)
  line L11 (183.4082, 242.4197) -> (191.4109, 250.6785)
  line L12 (196.282, 255.7056) -> (191.4109, 250.6785)
  line L13 (211.9449, 229.8812) -> (210.794, 230.9963)
  line L14 (211.8572, 219.7315) -> (219.8599, 227.9903)
  line L15 (224.731, 233.0174) -> (219.8599, 227.9903)
  line L16 (224.5964, 223.4007) -> (215.1233, 232.58)
  line L17 (218.4694, 237.6924) -> (213.1195, 232.1712)
  line L18 (209.5747, 229.9499) -> (215.8585, 223.8609)
  line L19 (229.5786, 228.3202) -> (219.8835, 237.7146)
  line L20 (209.718, 227.5831) -> (211.9449, 229.8812)
  line L21 (216.5938, 215.1419) -> (207.1207, 224.3212)
  line L22 (215.8585, 223.8609) -> (219.8599, 227.9903)
  line L23 (229.6009, 226.9062) -> (224.2509, 221.385)
  line L24 (208.5672, 228.6982) -> (209.718, 227.5831)
  line L25 (220.4783, 268.3213) -> (215.1284, 262.8001)
  line L26 (207.4712, 256.557) -> (197.9981, 265.7363)
  line L27 (215.6085, 274.4325) -> (210.7373, 269.4054)
  line L28 (199.4447, 270.1133) -> (200.5955, 268.9981)
  line L29 (215.4739, 264.8158) -> (206.0008, 273.9951)
  line L30 (220.456, 269.7353) -> (210.7609, 279.1297)
  line L31 (202.8223, 271.2962) -> (201.6715, 272.4114)
  line L32 (206.736, 265.276) -> (210.7373, 269.4054)
  line L33 (200.5955, 268.9981) -> (202.8223, 271.2962)
  line L34 (202.7347, 261.1466) -> (210.7373, 269.4054)
  line L35 (209.3469, 279.1074) -> (203.997, 273.5863)
  line L36 (200.4521, 271.365) -> (206.736, 265.276)
  line L37 (210.8569, 235.3578) -> (201.3837, 244.5371)
  line L38 (218.8595, 243.6166) -> (209.3864, 252.7959)
  line L39 (206.1203, 239.9475) -> (214.1229, 248.2063)
  line L40 (203.8378, 250.1659) -> (210.1216, 244.0769)
  line L41 (212.7325, 257.9083) -> (207.3826, 252.3871)
  line L42 (223.8639, 247.1221) -> (218.514, 241.601)
  line L43 (223.8417, 248.5362) -> (214.1466, 257.9306)
  line L44 (202.8303, 248.9141) -> (203.9811, 247.799)
  line L45 (206.2079, 250.0971) -> (205.0571, 251.2122)
  line L46 (203.9811, 247.799) -> (206.2079, 250.0971)
  line L47 (218.9941, 253.2334) -> (214.1229, 248.2063)
  line L48 (210.1216, 244.0769) -> (214.1229, 248.2063)
  arc A1 centre (187.4095, 246.5491) radius 8.75 clockwise from (196.1474, 246.0889) to (186.6743, 255.2682)
  arc A2 centre (190.7386, 259.6847) radius 1 clockwise from (190.0204, 260.3806) to (191.4345, 260.4028)
  arc A3 centre (200.4337, 250.2903) radius 1 clockwise from (201.1296, 251.0084) to (201.1519, 249.5944)
  circle C1 centre (187.4095, 246.5491) radius 3.5
  arc A4 centre (228.8827, 227.6021) radius 1 clockwise from (229.5786, 228.3202) to (229.6009, 226.9062)
  circle C2 centre (215.8585, 223.8609) radius 3.5
  arc A5 centre (219.1876, 236.9965) radius 1 clockwise from (218.4694, 237.6924) to (219.8835, 237.7146)
  arc A6 centre (215.8585, 223.8609) radius 8.75 clockwise from (224.5964, 223.4007) to (215.1233, 232.58)
  arc A7 centre (219.7602, 269.0171) radius 1 clockwise from (220.456, 269.7353) to (220.4783, 268.3213)
  circle C3 centre (206.736, 265.276) radius 3.5
  arc A8 centre (206.736, 265.276) radius 8.75 clockwise from (215.4739, 264.8158) to (206.0008, 273.9951)
  arc A9 centre (210.0651, 278.4115) radius 1 clockwise from (209.3469, 279.1074) to (210.7609, 279.1297)
  arc A10 centre (223.1458, 247.818) radius 1 clockwise from (223.8417, 248.5362) to (223.8639, 247.1221)
  circle C4 centre (210.1216, 244.0769) radius 3.5
  arc A11 centre (213.4507, 257.2124) radius 1 clockwise from (212.7325, 257.9083) to (214.1466, 257.9306)
  arc A12 centre (210.1216, 244.0769) radius 8.75 clockwise from (218.8595, 243.6166) to (209.3864, 252.7959)
  circle C5 centre (240.9626, 194.4625) radius 6
  circle C6 centre (235.5264, 213.4864) radius 6
  circle C7 centre (235.5264, 213.4864) radius 7
  circle C8 centre (240.9626, 194.4625) radius 7
  circle C9 centre (187.4095, 246.5491) radius 6
  circle C10 centre (206.736, 265.276) radius 6
  circle C11 centre (210.1216, 244.0769) radius 6
  circle C12 centre (215.8585, 223.8609) radius 6
  point P2 (187.4095, 246.5491)
  point P3 (187.4095, 246.5491)
  point P5 (195.8019, 244.0732)
  point P6 (184.6705, 254.8594)
  point P9 (178.6716, 247.0094)
  point P10 (188.1448, 237.8301)
  point P11 (191.4109, 250.6785)
  point P4 (191.8602, 259.9903)
  point P18 (182.345, 253.6845)
  point P21 (180.1182, 251.3864)
  point P22 (181.1257, 252.6381)
  point P23 (183.4082, 242.4197)
  point P24 (196.282, 255.7056)
  point P25 (187.4095, 246.5491)
  point P47 (215.8585, 223.8609)
  point P49 (215.8585, 223.8609)
  point P30 (224.2509, 221.385)
  point P31 (213.1195, 232.1712)
  point P28 (207.1207, 224.3212)
  point P34 (216.5938, 215.1419)
  point P39 (219.8599, 227.9903)
  point P48 (194.5013, 262.3095)
  point P44 (210.794, 230.9963)
  point P38 (208.5672, 228.6982)
  point P33 (209.5747, 229.9499)
  point P45 (211.8572, 219.7315)
  point P26 (224.731, 233.0174)
  point P27 (215.8585, 223.8609)
  point P72 (206.736, 265.276)
  point P74 (206.736, 265.276)
  point P55 (215.1284, 262.8001)
  point P56 (203.997, 273.5863)
  point P53 (197.9981, 265.7363)
  point P59 (207.4712, 256.557)
  point P64 (210.7373, 269.4054)
  point P73 (214.8641, 275.1538)
  point P69 (201.6715, 272.4114)
  point P63 (199.4447, 270.1133)
  point P58 (200.4521, 271.365)
  point P70 (202.7347, 261.1466)
  point P50 (215.6085, 274.4325)
  point P51 (206.736, 265.276)
  point P82 (210.1216, 244.0769)
  point P83 (210.1216, 244.0769)
  point P89 (218.514, 241.601)
  point P94 (207.3826, 252.3871)
  point P85 (201.3837, 244.5371)
  point P95 (210.8569, 235.3578)
  point P76 (214.1229, 248.2063)
  point P75 (205.0571, 251.2122)
  point P93 (202.8303, 248.9141)
  point P90 (203.8378, 250.1659)
  point P81 (206.1203, 239.9475)
  point P97 (218.9941, 253.2334)
  point P92 (210.1216, 244.0769)
  point P103 (206.736, 265.276)
  point P104 (210.1216, 244.0769)
  point P105 (215.8585, 223.8609)
  point P19 (183.4959, 252.5694)
  point P20 (181.269, 250.2713)
  point P35 (209.718, 227.5831)
  point P37 (211.9449, 229.8812)
  point P60 (200.5955, 268.9981)
  point P62 (202.8223, 271.2962)
  point P88 (203.9811, 247.799)
  point P96 (206.2079, 250.0971)
  coincident P2 P3
  coincident P5 A1
  coincident P6 A1
  perpendicular L1 L3
  coincident P9 A1
  coincident P10 A1
  perpendicular L1 L4
  coincident L3 P11
  coincident P4 L2
  tangent L2 A2
  tangent L2 A3
  equal A2 A3
  coincident A1 P18
  perpendicular L1 L5
  perpendicular L5 L6
  coincident A1 P21
  perpendicular L6 L7
  coincident A1 P22
  perpendicular L1 L8
  tangent A2 L9
  tangent A3 L10
  parallel L9 L10
  perpendicular L1 L2
  midpoint L4 P23
  midpoint P2 L11
  midpoint L2 P24
  perpendicular L2 L12
  equal L9 L10
  equal L5 L7
  coincident P3 P25
  coincident P47 P49
  coincident P30 A6
  coincident P31 A6
  perpendicular L16 L22
  coincident P28 A6
  coincident P34 A6
  perpendicular L21 L22
  coincident P39 L16
  coincident P48 L19
  tangent L19 A5
  tangent A4 L19
  equal A4 A5
  coincident P44 A6
  perpendicular L13 L22
  perpendicular L13 L20
  coincident P38 A6
  perpendicular L20 L24
  coincident P33 A6
  perpendicular L18 L22
  tangent L17 A5
  tangent A4 L23
  parallel L17 L23
  perpendicular L19 L22
  midpoint P45 L21
  midpoint P47 L14
  midpoint P26 L19
  perpendicular L15 L19
  equal L17 L23
  equal L13 L24
  coincident P27 P49
  coincident P72 P74
  coincident P55 A8
  coincident P56 A8
  perpendicular L29 L32
  coincident P53 A8
  coincident P59 A8
  perpendicular L26 L32
  coincident P64 L29
  coincident P73 L30
  tangent L30 A9
  tangent A7 L30
  equal A7 A9
  coincident P69 A8
  perpendicular L31 L32
  perpendicular L31 L33
  coincident P63 A8
  perpendicular L28 L33
  coincident P58 A8
  perpendicular L32 L36
  tangent A9 L35
  tangent A7 L25
  parallel L25 L35
  perpendicular L30 L32
  midpoint P70 L26
  midpoint P72 L34
  midpoint P50 L30
  perpendicular L27 L30
  equal L25 L35
  equal L28 L31
  coincident P51 P74
  coincident P82 P83
  coincident P89 A12
  coincident P94 A12
  perpendicular L38 L48
  coincident P85 A12
  coincident P95 A12
  perpendicular L37 L48
  coincident P76 L38
  tangent L43 A11
  tangent A10 L43
  equal A10 A11
  coincident P75 A12
  perpendicular L45 L48
  perpendicular L45 L46
  coincident P93 A12
  perpendicular L44 L46
  coincident P90 A12
  perpendicular L40 L48
  tangent L41 A11
  tangent A10 L42
  parallel L41 L42
  perpendicular L43 L48
  midpoint P81 L37
  midpoint P83 L39
  midpoint P97 L43
  perpendicular L43 L47
  equal L41 L42
  equal L44 L45
  coincident P82 P92
  parallel L17 L42
  parallel L25 L42
  parallel L10 L25
  concentric C6 C7
  concentric C5 C8
  concentric C1 C9
  coincident P74 P103
  coincident P82 P104
  coincident P49 P105
  dimension "d161" diameter A1 = 17.5
  dimension "d166" distance L3 L4 = 11.5
  dimension "d167" radius A2 = 1
  dimension "d168" distance P19 P20 = 3.2
  dimension "d169" distance L2 L3 = 7
  dimension "d170" distance L9 L10 = 15.5
  dimension "d171" distance P2 L6 = 7
  dimension "d172" diameter C1 = 7
  dimension "d173" diameter A6 = 17.5
  dimension "d174" distance L16 L21 = 11.5
  dimension "d175" radius A5 = 1
  dimension "d176" distance P35 P37 = 3.2
  dimension "d177" distance L16 L19 = 7
  dimension "d178" distance L17 L23 = 15.5
  dimension "d179" distance P47 L20 = 7
  dimension "d180" diameter C2 = 7
  dimension "d181" diameter A8 = 17.5
  dimension "d182" distance L26 L29 = 11.5
  dimension "d183" radius A9 = 1
  dimension "d184" distance P60 P62 = 3.2
  dimension "d185" distance L29 L30 = 7
  dimension "d186" distance L25 L35 = 15.5
  dimension "d187" distance P72 L33 = 7
  dimension "d188" diameter C3 = 7
  dimension "d189" diameter A12 = 17.5
  dimension "d190" distance L37 L38 = 11.5
  dimension "d191" radius A11 = 1
  dimension "d192" distance P88 P96 = 3.2
  dimension "d193" distance L38 L43 = 7
  dimension "d194" distance L41 L42 = 15.5
  dimension "d195" distance P83 L46 = 7
  dimension "d196" diameter C4 = 7
  dimension "d208" diameter C5 = 12
  dimension "d209" diameter C6 = 12
  dimension "d212" diameter C7 = 14
  dimension "d213" diameter C8 = 14
  dimension "d219" diameter C9 = 12
  dimension "d220" diameter C10 = 12
  dimension "d221" diameter C11 = 12
  dimension "d222" diameter C12 = 12
extrude "Extrude7" cut sketch "potentiometers" profile of A1 L2 L3 L4 A2 A3 L5 L6 L7 L9 L10 C1 L13 L16 L17 A4 L19 C2 A5 L20 L21 L23 L24 A6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 against normal blind 2
extrude "Extrude8" cut sketch "potentiometers" profile of C1 C2 C3 C4 against normal blind 54
extrude "Extrude9" sketch "potentiometers" profile of A1 L3 L4 L5 L6 L7 C1 L13 L16 C2 L20 L21 L24 A6 L26 C3 A8 L28 L29 L31 L33 L37 L38 C4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 along a picked direction blind -2
extrude "Extrude10" sketch "potentiometers" profile of A1 L5 L6 L7 L13 L20 L24 A6 A8 L28 L31 L33 L44 L45 L46 A12 along a picked direction blind -2.5
extrude "Extrude11" cut sketch "potentiometers" profile of C5 C6 against normal blind 80
extrude "Extrude12" sketch "potentiometers" profile of C5 C6 C7 C8 along a picked direction blind 1.5
chamfer "Chamfer2" distance 0.4
chamfer "Chamfer3" distance 0.4
extrude "Extrude13" sketch "potentiometers" profile of L3 L4 C1 L16 C2 L21 L26 C3 L29 L37 L38 C4 C9 C10 C11 C12 along a picked direction blind 0.5
hole "Hole3" HoleDepth 30 HoleDiameter 8 TipAngle 180 CBDepth 1 CBDiameter 11.5
sketch "slot line" plane through (0, 0.0002, 0) normal (0, 1, 0) x axis (-1, 0, 0)
  line L1 (-252.5241, 186.2094) -> (-240.9703, 179.5388)
  curve K1 (-174.1727, 244.2806) -> (-252.5241, 186.2094)
  line L2 (-182.7946, 238.5269) -> (-174.1727, 244.2806)
  line L3 (-294.8797, 38.6359) -> (-284.2856, 37.2412)
  line L4 (-296.7753, 20.7526) -> (-296.6755, 20.7456)
  line L5 (-294.9932, 38.6508) -> (-294.9788, 38.649)
  line L6 (-287.6222, 131.4177) -> (-271.3298, 122.0113)
  line L7 (-290.1222, 127.0876) -> (-287.6222, 131.4177)
  line L8 (-281.1738, 104.6007) -> (-284.6318, 106.5972)
  line L9 (-297.4, 0) -> (-300, 0)
  line L10 (-295.3663, -8.8866) -> (-297.2653, -8.9505)
  line L11 (-288.5852, 0) -> (-295.5, 0)
  line L12 (-286.9844, -20.0679) -> (-287.8822, -20.1307)
  line L13 (-286.0549, -19.0005) -> (-286.9844, -20.0679)
  line L14 (-284.5852, 0) -> (-286.6852, 0)
  line L15 (-142.7926, 247.324) -> (-142.2926, 246.458)
  line L16 (-144.1577, 247.6885) -> (-142.7926, 247.324)
  line L17 (-170.2702, 243.9555) -> (-163.9732, 235.0401)
  line L18 (-158.9396, 253.2593) -> (-158.1458, 251.9845)
  line L19 (-159.7885, 252.7308) -> (-158.9396, 253.2593)
  line L20 (-160.3134, 253.5737) -> (-159.7885, 252.7308)
  curve K2 (-171.7126, 245.9976) -> (-255.1222, 187.7094)
  line L21 (-257.6222, 183.3793) -> (-255.1222, 187.7094)
  line L22 (-241.3298, 173.9728) -> (-257.6222, 183.3793)
  line L23 (-174.3946, 227.5779) -> (-180.9692, 236.1462)
  line L24 (-269.3835, 97.7936) -> (-269.4715, 97.8444)
  line L25 (-285.9868, 19.9981) -> (-285.8871, 19.9912)
  line L26 (-288.5591, 0.8045) -> (-285.5841, 0.8045)
  line L27 (-288.5852, 0) -> (-288.5591, 0.8045)
  line L28 (-287.6852, 0.8045) -> (-287.6852, 0)
  line L29 (-286.0549, -19.0005) -> (-287.0527, -19.0667)
  line L30 (-296.7436, -19.7479) -> (-295.678, -20.6758)
  line L31 (-294.7802, -20.613) -> (-295.678, -20.6758)
  line L32 (-297.1947, -11.0493) -> (-295.2957, -10.9855)
  line L33 (-295.7458, -19.6815) -> (-296.7436, -19.7479)
  line L34 (-296.4, 0.9531) -> (-296.4, 0)
  line L35 (-298.9985, 0.9531) -> (-296.4, 0.9531)
  line L36 (-289.2562, 126.5876) -> (-286.7562, 130.9177)
  line L37 (-280.6738, 105.4667) -> (-284.1318, 107.4633)
  curve K3 (-172.5326, 245.4252) -> (-254.2562, 187.2094)
  line L38 (-157.157, 254.3694) -> (-156.3081, 254.898)
  line L39 (-156.3631, 253.0945) -> (-157.157, 254.3694)
  line L40 (-149.6152, 257.1411) -> (-149.25, 258.5086)
  line L41 (-150, 259.8076) -> (-149.25, 258.5086)
  line L42 (-156.3081, 254.898) -> (-156.833, 255.7409)
  line L43 (-149.4511, 258.8569) -> (-156.3081, 254.898)
  line L44 (-256.7562, 182.8793) -> (-254.2562, 187.2094)
  line L45 (-171.1402, 245.1776) -> (-159.7885, 252.7308)
  arc A1 centre (0.1681, -0.0971) radius 300.6938 clockwise from (-240.9703, 179.5388) to (-182.7946, 238.5269)
  arc A2 centre (0, 0) radius 297.4 clockwise from (-296.6755, 20.7456) to (-294.8797, 38.6359)
  arc A3 centre (0, 0) radius 297.5 clockwise from (-296.7753, 20.7526) to (-294.9788, 38.649)
  arc A4 centre (0.1681, -0.0971) radius 297.6938 clockwise from (-294.9932, 38.6508) to (-271.3298, 122.0113)
  arc A5 centre (-277.1318, 119.5876) radius 15 clockwise from (-284.6318, 106.5972) to (-290.1222, 127.0876)
  arc A6 centre (0, 0) radius 300 clockwise from (-300, 0) to (-281.1738, 104.6007)
  arc A7 centre (0, 0) radius 297.4 clockwise from (-297.2653, -8.9505) to (-297.4, 0)
  arc A8 centre (0, 0) radius 295.5 clockwise from (-295.3663, -8.8866) to (-295.5, 0)
  arc A9 centre (0, 0) radius 288.5852 clockwise from (-287.8822, -20.1307) to (-288.5852, 0)
  arc A10 centre (0, 0) radius 286.6852 clockwise from (-286.0549, -19.0005) to (-286.6852, 0)
  arc A11 centre (0, 0) radius 284.5852 clockwise from (-284.5852, 0) to (-142.2926, 246.458)
  arc A12 centre (0, 0) radius 286.5852 clockwise from (-163.9732, 235.0401) to (-144.1577, 247.6885)
  arc A13 centre (0, 0) radius 297.5 clockwise from (-170.2702, 243.9555) to (-158.1458, 251.9845)
  arc A14 centre (0, 0) radius 300 clockwise from (-171.7126, 245.9976) to (-160.3134, 253.5737)
  arc A15 centre (0.1681, -0.0971) radius 297.6938 clockwise from (-241.3298, 173.9728) to (-180.9692, 236.1462)
  arc A16 centre (0.1681, -0.0971) radius 286.8938 clockwise from (-284.2856, 37.2412) to (-174.3946, 227.5779)
  arc A17 centre (0, 0) radius 286.6852 clockwise from (-285.9868, 19.9981) to (-269.4715, 97.8444)
  arc A18 centre (0, 0) radius 286.5852 clockwise from (-285.8871, 19.9912) to (-269.3835, 97.7936)
  arc A19 centre (0, 0) radius 285.5852 clockwise from (-285.5841, 0.8045) to (-142.7926, 247.324)
  arc A20 centre (0, 0) radius 287.6852 clockwise from (-287.0527, -19.0667) to (-287.6852, 0)
  arc A21 centre (0, 0) radius 297.4 clockwise from (-296.7436, -19.7479) to (-297.1947, -11.0493)
  arc A22 centre (0, 0) radius 295.5 clockwise from (-294.7802, -20.613) to (-295.2957, -10.9855)
  arc A23 centre (0, 0) radius 296.4 clockwise from (-295.7458, -19.6815) to (-296.1954, -11.0122)
  arc A24 centre (0, 0) radius 299 clockwise from (-298.9985, 0.9531) to (-280.2365, 104.2521)
  arc A25 centre (0, 0) radius 296.4 clockwise from (-296.2657, -8.9204) to (-296.4, 0)
  arc A26 centre (-277.1318, 119.5876) radius 14 clockwise from (-284.1318, 107.4633) to (-289.2562, 126.5876)
  arc A27 centre (-281.1738, 104.6007) radius 1 clockwise from (-280.6738, 105.4667) to (-280.2365, 104.2521)
  arc A28 centre (0, 0) radius 297.5 clockwise from (-156.3631, 253.0945) to (-149.6152, 257.1411)
  arc A29 centre (0, 0) radius 300 clockwise from (-156.833, 255.7409) to (-150, 259.8076)
  arc A30 centre (-171.7126, 245.9976) radius 1 clockwise from (-171.1402, 245.1776) to (-172.5326, 245.4252)
  point P25 (-288.5852, 0)
  point P55 (-288.5852, 0)
  point P28 (-286.0549, -19.0005)
  point P60 (-286.0549, -19.0005)
  point P62 (-296.7436, -19.7479)
  point P70 (-296.7436, -19.7479)
  point P87 (-156.3081, 254.898)
  point P95 (-156.3081, 254.898)
  point P96 (-149.4511, 258.8569)
  point P98 (-256.7562, 182.8793)
  point P38 (-159.7885, 252.7308)
  point P99 (-159.7885, 252.7308)
  horizontal L26
  coincident P25 P55
  coincident P28 P60
  concentric A10 A20
  tangent L28 A20
  coincident P62 P70
  tangent A25 L34
  vertical L34
  perpendicular L34 L35
  concentric A6 A24
  concentric A11 A19
  tangent A24 A27
  coincident P87 P95
  coincident L41 P96
  perpendicular L41 L43
  coincident L22 P98
  perpendicular L22 L44
  coincident P38 P99
  dimension "d233" = -1
  dimension "d235" = -1
  dimension "d236" = -1
  dimension "d237" = 1
extrude "Extrude15" add sketch "slot line" profile of L6 L7 A5 L8 A6 L9 A7 L10 A10 L14 A11 L15 L20 A14 K2 L21 L22 A19 L26 L28 A20 L29 A21 L32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 along normal blind 1.5
extrude "Extrude14" cut sketch "slot line" profile of L6 L7 A5 L8 A6 L9 A7 L10 A10 L14 A11 L15 L20 A14 K2 L21 L22 A19 L26 L28 A20 L29 A21 L32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 along normal blind 1.5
